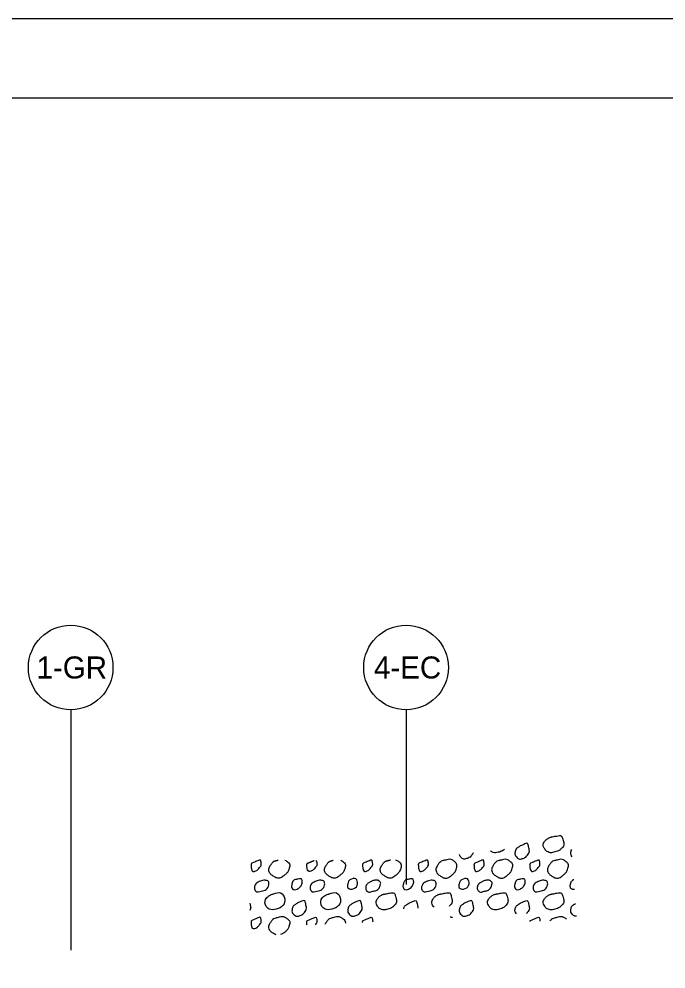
# Model space of a CAD drawing. Extents: x 0 to 3369, y -440 to 440.
# Drawn here: x 466.9 to 549, y 319.4 to 440 of the extents above; entities that cross this region are included whole.
import ezdxf

# ---------------------------------------------------------------- set-up
doc = ezdxf.new("R2010")
doc.units = 0
for name, color, linetype in [('GE_P_Alignment', 7, 'Continuous'), ('PF_X_Ground_Line', 7, 'Continuous'), ('PV_P_EOP', 7, 'Continuous'), ('SC_Scratch1', 7, 'Continuous')]:
    doc.layers.add(name, color=color, linetype=linetype)

msp = doc.modelspace()

# ---------------------------------------------------------------- linework, layer by layer
at = {"layer": 'GE_P_Alignment'}
for points, degree in [([(530.47, 335), (530.7, 335.1), (530.94, 335.2), (531.17, 335.3), (531.42, 335.4), (531.53, 334.87), (531.59, 334.62), (531.64, 334.36), (531.58, 334.06), (531.37, 333.81), (531.17, 333.57), (530.94, 333.46), (530.7, 333.39), (530.51, 333.33), (530.26, 333.32), (530.08, 333.5), (529.85, 333.73), (529.76, 333.99), (529.81, 334.22), (529.85, 334.4), (529.93, 334.64), (530.1, 334.76), (530.22, 334.84), (530.35, 334.92), (530.47, 335)], 3), ([(534.51, 336.16), (534.81, 336.21), (535.12, 336.27), (535.42, 336.31), (535.72, 336.35), (535.86, 335.84), (535.94, 335.55), (536.01, 335.29), (535.96, 334.98), (535.74, 334.74), (535.48, 334.44), (535.18, 334.33), (534.85, 334.23), (534.57, 334.15), (534.25, 334.12), (533.97, 334.24), (533.8, 334.31), (533.68, 334.44), (533.57, 334.6), (533.4, 334.86), (533.35, 335.23), (533.5, 335.49), (533.6, 335.65), (533.74, 335.8), (533.91, 335.91), (534.06, 336.01), (534.2, 336.09), (534.36, 336.13), (534.42, 336.14), (534.47, 336.15), (534.53, 336.16)], 3), ([(528.47, 334.55), (528.26, 334.39), (528.03, 334.31), (527.78, 334.23), (527.5, 334.15), (527.18, 334.12), (526.9, 334.24), (526.83, 334.27), (526.76, 334.31), (526.7, 334.36)], 3), ([(537.05, 333.61), (536.9, 333.81), (536.84, 334.03), (536.88, 334.22), (536.9, 334.32), (536.93, 334.43), (536.99, 334.53)], 3), ([(496.4, 332.81), (496.71, 332.93), (497.03, 333.07), (497.35, 333.19), (497.5, 333.25), (497.58, 332.9), (497.6, 332.75), (497.62, 332.55), (497.46, 332.35), (497.3, 332.15), (497.08, 331.88), (496.51, 331.69), (496.4, 331.98), (496.34, 332.14), (496.33, 332.3), (496.32, 332.46), (496.32, 332.54), (496.29, 332.63), (496.33, 332.7), (496.35, 332.74), (496.37, 332.77), (496.4, 332.81)], 3), ([(500.61, 333.19), (500.72, 333.15), (500.83, 333.07), (500.95, 332.98), (501.22, 332.76), (501.23, 332.42), (501.16, 332.18), (501.07, 331.86), (500.87, 331.56), (500.57, 331.31), (500.19, 330.98), (499.66, 330.85), (499.27, 331.08), (498.96, 331.27), (498.63, 331.55), (498.57, 331.88), (498.53, 332.09), (498.63, 332.33), (498.76, 332.52), (498.84, 332.65), (498.92, 332.79), (499.03, 332.9), (499.09, 332.95), (499.14, 333.01), (499.19, 333.06)], 3), ([(499.19, 333.06), (499.38, 333.11), (499.56, 333.15), (499.75, 333.2)], 2), ([(504.53, 333.16), (504.61, 333.07), (504.66, 332.86), (504.67, 332.75), (504.69, 332.55), (504.53, 332.35), (504.37, 332.15), (504.15, 331.88), (503.59, 331.69), (503.47, 331.98), (503.41, 332.14), (503.4, 332.3), (503.39, 332.46), (503.39, 332.54), (503.36, 332.63), (503.4, 332.7), (503.42, 332.74), (503.44, 332.77), (503.47, 332.81)], 3), ([(503.47, 332.81), (503.75, 332.92), (504.04, 333.05), (504.33, 333.16)], 2), ([(507.7, 333.18), (507.81, 333.14), (507.91, 333.07), (508.02, 332.98), (508.29, 332.76), (508.3, 332.42), (508.23, 332.18), (508.14, 331.86), (507.95, 331.56), (507.64, 331.31), (507.26, 330.98), (506.73, 330.85), (506.35, 331.08), (506.03, 331.27), (505.7, 331.55), (505.64, 331.88), (505.6, 332.09), (505.71, 332.33), (505.83, 332.52), (505.91, 332.65), (505.99, 332.79), (506.1, 332.9), (506.16, 332.95), (506.21, 333.01), (506.27, 333.06)], 3), ([(506.27, 333.06), (506.42, 333.1), (506.57, 333.14), (506.72, 333.18)], 2), ([(510.54, 332.81), (510.86, 332.93), (511.17, 333.07), (511.49, 333.19), (511.64, 333.25), (511.73, 332.9), (511.74, 332.75), (511.76, 332.55), (511.61, 332.35), (511.44, 332.15), (511.22, 331.88), (510.66, 331.69), (510.54, 331.98), (510.48, 332.14), (510.47, 332.3), (510.46, 332.46), (510.46, 332.54), (510.43, 332.63), (510.47, 332.7), (510.49, 332.74), (510.52, 332.77), (510.54, 332.81)], 3), ([(514.62, 333.24), (514.78, 333.19), (514.94, 333.11), (515.09, 332.98), (515.36, 332.76), (515.38, 332.42), (515.31, 332.18), (515.22, 331.86), (515.02, 331.56), (514.71, 331.31), (514.33, 330.98), (513.81, 330.85), (513.42, 331.08), (513.1, 331.27), (512.77, 331.55), (512.71, 331.88), (512.67, 332.09), (512.78, 332.33), (512.9, 332.52), (512.98, 332.65), (513.06, 332.79), (513.18, 332.9), (513.23, 332.95), (513.28, 333.01), (513.34, 333.06)], 3), ([(513.34, 333.06), (513.56, 333.12), (513.79, 333.18), (514.01, 333.23)], 2), ([(517.61, 332.81), (517.93, 332.93), (518.24, 333.07), (518.56, 333.19), (518.72, 333.25), (518.8, 332.9), (518.81, 332.75), (518.83, 332.55), (518.68, 332.35), (518.51, 332.15), (518.29, 331.88), (517.73, 331.69), (517.61, 331.98), (517.55, 332.14), (517.54, 332.3), (517.54, 332.46), (517.53, 332.54), (517.5, 332.63), (517.54, 332.7), (517.56, 332.74), (517.59, 332.77), (517.61, 332.81)], 3), ([(520.41, 333.06), (520.65, 333.12), (520.88, 333.18), (521.12, 333.24), (521.47, 333.33), (521.82, 333.27), (522.16, 332.98), (522.43, 332.76), (522.45, 332.42), (522.38, 332.18), (522.29, 331.86), (522.09, 331.56), (521.79, 331.31), (521.41, 330.98), (520.88, 330.85), (520.49, 331.08), (520.17, 331.27), (519.84, 331.55), (519.78, 331.88), (519.74, 332.09), (519.85, 332.33), (519.97, 332.52), (520.06, 332.65), (520.13, 332.79), (520.25, 332.9), (520.3, 332.95), (520.35, 333.01), (520.41, 333.06)], 3), ([(524.48, 334.12), (524.44, 334.01), (524.38, 333.91), (524.29, 333.81), (524.09, 333.57), (523.87, 333.46), (523.63, 333.39), (523.43, 333.33), (523.19, 333.32), (523.01, 333.5), (522.87, 333.64), (522.78, 333.79), (522.75, 333.93)], 3), ([(524.68, 332.81), (525, 332.93), (525.32, 333.07), (525.63, 333.19), (525.79, 333.25), (525.87, 332.9), (525.88, 332.75), (525.9, 332.55), (525.75, 332.35), (525.59, 332.15), (525.36, 331.88), (524.8, 331.69), (524.69, 331.98), (524.62, 332.14), (524.61, 332.3), (524.61, 332.46), (524.6, 332.54), (524.57, 332.63), (524.62, 332.7), (524.64, 332.74), (524.66, 332.77), (524.68, 332.81)], 3), ([(527.48, 333.06), (527.72, 333.12), (527.95, 333.18), (528.19, 333.24), (528.54, 333.33), (528.89, 333.27), (529.23, 332.98), (529.5, 332.76), (529.52, 332.42), (529.45, 332.18), (529.36, 331.86), (529.16, 331.56), (528.86, 331.31), (528.48, 330.98), (527.95, 330.85), (527.56, 331.08), (527.24, 331.27), (526.91, 331.55), (526.85, 331.88), (526.81, 332.09), (526.92, 332.33), (527.04, 332.52), (527.13, 332.65), (527.2, 332.79), (527.32, 332.9), (527.37, 332.95), (527.43, 333.01), (527.48, 333.06)], 3), ([(531.75, 332.81), (532.07, 332.93), (532.39, 333.07), (532.7, 333.19), (532.86, 333.25), (532.94, 332.9), (532.95, 332.75), (532.97, 332.55), (532.82, 332.35), (532.66, 332.15), (532.43, 331.88), (531.87, 331.69), (531.76, 331.98), (531.7, 332.14), (531.68, 332.3), (531.68, 332.46), (531.68, 332.54), (531.64, 332.63), (531.69, 332.7), (531.71, 332.74), (531.73, 332.77), (531.75, 332.81)], 3), ([(534.55, 333.06), (534.79, 333.12), (535.03, 333.18), (535.26, 333.24), (535.61, 333.33), (535.96, 333.27), (536.3, 332.98), (536.57, 332.76), (536.59, 332.42), (536.52, 332.18), (536.43, 331.86), (536.23, 331.56), (535.93, 331.31), (535.55, 330.98), (535.02, 330.85), (534.63, 331.08), (534.32, 331.27), (533.98, 331.55), (533.92, 331.88), (533.89, 332.09), (533.99, 332.33), (534.11, 332.52), (534.2, 332.65), (534.28, 332.79), (534.39, 332.9), (534.44, 332.95), (534.5, 333.01), (534.55, 333.06)], 3), ([(501.78, 330.71), (502.03, 330.75), (502.28, 330.79), (502.54, 330.82), (502.77, 330.85), (502.82, 330.36), (502.75, 330.17), (502.67, 329.95), (502.47, 329.73), (502.27, 329.58), (502.06, 329.42), (501.62, 329.44), (501.49, 329.69), (501.42, 329.85), (501.46, 330.03), (501.5, 330.18), (501.53, 330.29), (501.54, 330.42), (501.62, 330.51), (501.67, 330.58), (501.72, 330.64), (501.78, 330.71)], 3), ([(511.12, 330.28), (511.29, 330.36), (511.45, 330.44), (511.62, 330.53), (511.8, 330.62), (512.02, 330.64), (512.22, 330.64), (512.37, 330.65), (512.51, 330.61), (512.65, 330.48), (512.77, 330.36), (512.75, 330.2), (512.71, 330.07), (512.65, 329.86), (512.58, 329.65), (512.37, 329.48), (512.17, 329.31), (511.96, 329.29), (511.75, 329.24), (511.52, 329.19), (511.26, 329.06), (511.04, 329.25), (510.9, 329.38), (510.87, 329.54), (510.87, 329.68), (510.87, 329.82), (510.89, 329.97), (510.97, 330.08), (511.02, 330.15), (511.07, 330.21), (511.12, 330.28)], 3), ([(515.92, 330.71), (516.17, 330.75), (516.43, 330.79), (516.68, 330.82), (516.91, 330.85), (516.96, 330.36), (516.89, 330.17), (516.81, 329.95), (516.61, 329.73), (516.41, 329.58), (516.2, 329.42), (515.76, 329.44), (515.64, 329.69), (515.56, 329.85), (515.6, 330.03), (515.64, 330.18), (515.67, 330.29), (515.69, 330.42), (515.76, 330.51), (515.81, 330.58), (515.86, 330.64), (515.92, 330.71)], 3), ([(525.27, 330.28), (525.43, 330.36), (525.6, 330.44), (525.77, 330.53), (525.95, 330.62), (526.17, 330.64), (526.37, 330.64), (526.51, 330.65), (526.66, 330.61), (526.79, 330.48), (526.91, 330.36), (526.89, 330.2), (526.86, 330.07), (526.8, 329.86), (526.72, 329.65), (526.52, 329.48), (526.31, 329.31), (526.1, 329.29), (525.89, 329.24), (525.66, 329.19), (525.41, 329.06), (525.19, 329.25), (525.04, 329.38), (525.01, 329.54), (525.01, 329.68), (525.02, 329.82), (525.03, 329.97), (525.12, 330.08), (525.17, 330.15), (525.22, 330.21), (525.27, 330.28)], 3), ([(530.06, 330.71), (530.32, 330.75), (530.57, 330.79), (530.83, 330.82), (531.05, 330.85), (531.11, 330.36), (531.03, 330.17), (530.95, 329.95), (530.76, 329.73), (530.55, 329.58), (530.34, 329.42), (529.9, 329.44), (529.78, 329.69), (529.7, 329.85), (529.74, 330.03), (529.79, 330.18), (529.82, 330.29), (529.83, 330.42), (529.9, 330.51), (529.95, 330.58), (530.01, 330.64), (530.06, 330.71)], 3), ([(537.34, 329.48), (537.14, 329.46), (536.93, 329.53), (536.85, 329.69), (536.78, 329.85), (536.81, 330.03), (536.86, 330.18), (536.89, 330.29), (536.9, 330.42), (536.97, 330.51), (537.03, 330.58), (537.08, 330.64), (537.13, 330.71)], 3), ([(537.13, 330.71), (537.17, 330.72), (537.21, 330.72), (537.25, 330.73)], 2), ([(502.18, 327.73), (502.42, 327.84), (502.65, 327.94), (502.89, 328.04), (503.13, 328.14), (503.25, 327.61), (503.3, 327.36), (503.36, 327.1), (503.29, 326.8), (503.08, 326.55), (502.88, 326.31), (502.65, 326.2), (502.41, 326.12), (502.22, 326.07), (501.98, 326.06), (501.79, 326.24), (501.56, 326.47), (501.48, 326.73), (501.52, 326.96), (501.56, 327.14), (501.64, 327.38), (501.82, 327.5), (501.94, 327.58), (502.06, 327.65), (502.18, 327.73)], 3), ([(509.26, 327.73), (509.49, 327.84), (509.72, 327.94), (509.96, 328.04), (510.2, 328.14), (510.32, 327.61), (510.37, 327.36), (510.43, 327.1), (510.36, 326.8), (510.15, 326.55), (509.95, 326.31), (509.72, 326.2), (509.48, 326.12), (509.29, 326.07), (509.05, 326.06), (508.86, 326.24), (508.63, 326.47), (508.55, 326.73), (508.6, 326.96), (508.63, 327.14), (508.72, 327.38), (508.89, 327.5), (509.01, 327.58), (509.13, 327.65), (509.26, 327.73)], 3), ([(513.3, 328.9), (513.6, 328.95), (513.9, 329.01), (514.2, 329.05), (514.51, 329.09), (514.65, 328.57), (514.72, 328.29), (514.79, 328.03), (514.75, 327.72), (514.53, 327.48), (514.26, 327.18), (513.97, 327.07), (513.64, 326.97), (513.35, 326.89), (513.04, 326.86), (512.76, 326.98), (512.59, 327.05), (512.46, 327.17), (512.36, 327.33), (512.19, 327.6), (512.13, 327.97), (512.29, 328.22), (512.39, 328.39), (512.52, 328.54), (512.7, 328.65), (512.84, 328.75), (512.98, 328.83), (513.15, 328.87), (513.2, 328.88), (513.26, 328.89), (513.31, 328.9)], 3), ([(516.33, 327.73), (516.56, 327.84), (516.8, 327.94), (517.03, 328.04), (517.27, 328.14), (517.39, 327.61), (517.45, 327.36), (517.46, 327.28), (517.47, 327.19), (517.46, 327.1)], 3), ([(519.52, 327.22), (519.49, 327.25), (519.46, 327.29), (519.43, 327.33), (519.26, 327.6), (519.21, 327.97), (519.36, 328.22), (519.46, 328.39), (519.59, 328.54), (519.77, 328.65), (519.91, 328.75), (520.06, 328.83), (520.22, 328.87), (520.27, 328.88), (520.33, 328.89), (520.38, 328.9)], 3), ([(520.37, 328.9), (520.67, 328.95), (520.97, 329.01), (521.28, 329.05), (521.58, 329.09), (521.72, 328.57), (521.79, 328.29), (521.86, 328.03), (521.82, 327.72), (521.6, 327.48), (521.55, 327.42), (521.49, 327.37), (521.44, 327.32)], 3), ([(523.4, 327.73), (523.63, 327.84), (523.87, 327.94), (524.1, 328.04), (524.34, 328.14), (524.46, 327.61), (524.52, 327.36), (524.57, 327.1), (524.51, 326.8), (524.29, 326.55), (524.09, 326.31), (523.87, 326.2), (523.63, 326.12), (523.43, 326.07), (523.19, 326.06), (523.01, 326.24), (522.78, 326.47), (522.69, 326.73), (522.74, 326.96), (522.77, 327.14), (522.86, 327.38), (523.03, 327.5), (523.15, 327.58), (523.28, 327.65), (523.4, 327.73)], 3), ([(527.44, 328.9), (527.74, 328.95), (528.04, 329.01), (528.35, 329.05), (528.65, 329.09), (528.79, 328.57), (528.87, 328.29), (528.93, 328.03), (528.89, 327.72), (528.67, 327.48), (528.41, 327.18), (528.11, 327.07), (527.78, 326.97), (527.5, 326.89), (527.18, 326.86), (526.9, 326.98), (526.73, 327.05), (526.61, 327.17), (526.5, 327.33), (526.33, 327.6), (526.28, 327.97), (526.43, 328.22), (526.53, 328.39), (526.66, 328.54), (526.84, 328.65), (526.99, 328.75), (527.13, 328.83), (527.29, 328.87), (527.35, 328.88), (527.4, 328.89), (527.46, 328.9)], 3), ([(530.47, 327.73), (530.7, 327.84), (530.94, 327.94), (531.17, 328.04), (531.42, 328.14), (531.53, 327.61), (531.59, 327.36), (531.64, 327.1), (531.58, 326.8), (531.37, 326.55), (531.33, 326.51), (531.3, 326.47), (531.26, 326.44)], 3), ([(534.51, 328.9), (534.81, 328.95), (535.12, 329.01), (535.42, 329.05), (535.72, 329.09), (535.86, 328.57), (535.94, 328.29), (536.01, 328.03), (535.96, 327.72), (535.74, 327.48), (535.48, 327.18), (535.18, 327.07), (534.85, 326.97), (534.57, 326.89), (534.25, 326.86), (533.97, 326.98), (533.8, 327.05), (533.68, 327.17), (533.57, 327.33), (533.4, 327.6), (533.35, 327.97), (533.5, 328.22), (533.6, 328.39), (533.74, 328.54), (533.91, 328.65), (534.06, 328.75), (534.2, 328.83), (534.36, 328.87), (534.42, 328.88), (534.47, 328.89), (534.53, 328.9)], 3), ([(496.13, 327.75), (496.17, 327.61), (496.21, 327.46), (496.23, 327.36), (496.27, 327.18), (496.25, 326.98), (496.16, 326.79)], 3), ([(515.68, 327.01), (515.72, 327.18), (515.8, 327.39), (515.96, 327.5), (516.08, 327.58), (516.2, 327.65), (516.33, 327.73)], 3), ([(529.97, 326.37), (529.82, 326.56), (529.77, 326.77), (529.81, 326.96), (529.85, 327.14), (529.93, 327.38), (530.1, 327.5), (530.22, 327.58), (530.35, 327.65), (530.47, 327.73)], 3), ([(537.58, 326.09), (537.43, 326.08), (537.28, 326.12), (537.15, 326.24), (536.92, 326.47), (536.84, 326.73), (536.88, 326.96), (536.92, 327.14), (537, 327.38), (537.17, 327.5), (537.27, 327.56), (537.37, 327.62), (537.47, 327.69)], 3), ([(496.4, 325.54), (496.71, 325.67), (497.03, 325.81), (497.35, 325.93), (497.5, 325.99), (497.58, 325.64), (497.6, 325.49), (497.62, 325.29), (497.46, 325.09), (497.3, 324.89), (497.08, 324.62), (496.51, 324.42), (496.4, 324.72), (496.34, 324.88), (496.33, 325.04), (496.32, 325.2), (496.32, 325.28), (496.29, 325.37), (496.33, 325.44), (496.35, 325.48), (496.37, 325.51), (496.4, 325.54)], 3), ([(499.49, 323.73), (499.41, 323.75), (499.34, 323.78), (499.27, 323.82), (498.96, 324.01), (498.63, 324.29), (498.57, 324.62), (498.53, 324.83), (498.63, 325.06), (498.76, 325.26), (498.84, 325.39), (498.92, 325.53), (499.03, 325.64), (499.09, 325.69), (499.14, 325.74), (499.19, 325.8)], 3), ([(499.19, 325.8), (499.43, 325.86), (499.67, 325.92), (499.91, 325.98), (500.25, 326.07), (500.6, 326.01), (500.95, 325.72), (501.22, 325.49), (501.23, 325.16), (501.16, 324.91), (501.07, 324.6), (500.87, 324.3), (500.57, 324.04), (500.42, 323.91), (500.24, 323.82), (500.06, 323.76)], 3), ([(503.47, 325.54), (503.78, 325.67), (504.1, 325.81), (504.42, 325.93), (504.57, 325.99), (504.65, 325.64), (504.67, 325.49), (504.68, 325.32), (504.58, 325.15), (504.44, 324.98)], 3), ([(505.71, 325.05), (505.75, 325.12), (505.79, 325.19), (505.83, 325.26), (505.91, 325.39), (505.99, 325.53), (506.1, 325.64), (506.16, 325.69), (506.21, 325.74), (506.27, 325.8)], 3), ([(506.27, 325.8), (506.5, 325.86), (506.74, 325.92), (506.98, 325.98), (507.32, 326.07), (507.67, 326.01), (508.02, 325.72), (508.2, 325.57), (508.26, 325.37), (508.27, 325.19)], 3), ([(510.54, 325.54), (510.86, 325.67), (511.17, 325.81), (511.49, 325.93), (511.64, 325.99), (511.73, 325.64), (511.74, 325.49), (511.74, 325.45), (511.74, 325.41), (511.73, 325.37)], 3), ([(521.56, 326.01), (521.66, 325.99), (521.75, 325.97), (521.84, 325.92)], 2), ([(531.75, 325.54), (532.07, 325.67), (532.39, 325.81), (532.7, 325.93), (532.86, 325.99), (532.94, 325.64), (532.95, 325.49), (532.96, 325.48), (532.96, 325.47), (532.96, 325.45)], 3), ([(534.27, 325.5), (534.3, 325.55), (534.34, 325.6), (534.39, 325.64), (534.44, 325.69), (534.5, 325.74), (534.55, 325.8)], 3), ([(534.55, 325.8), (534.79, 325.86), (535.03, 325.92), (535.26, 325.98), (535.61, 326.07), (535.96, 326.01), (536.3, 325.72), (536.31, 325.72), (536.31, 325.71), (536.32, 325.71)], 3), ([(503.42, 324.92), (503.4, 325.01), (503.4, 325.11), (503.39, 325.2), (503.39, 325.28), (503.36, 325.37), (503.4, 325.44), (503.42, 325.48), (503.44, 325.51), (503.47, 325.54)], 3), ([(510.45, 325.3), (510.45, 325.35), (510.45, 325.4), (510.47, 325.44), (510.49, 325.48), (510.52, 325.51), (510.54, 325.54)], 3), ([(531.69, 325.45), (531.71, 325.49), (531.73, 325.51), (531.75, 325.54)], 2)]:
    msp.add_open_spline(points, degree=degree, dxfattribs=at)
for points in [[(496.98, 330.28), (497.48, 330.53), (498.08, 330.64), (498.5, 330.48), (498.57, 330.07), (498.23, 329.48), (497.6, 329.24), (496.9, 329.25), (496.73, 329.68), (496.83, 330.08), (496.98, 330.28)], [(504.05, 330.28), (504.55, 330.53), (505.15, 330.64), (505.57, 330.48), (505.64, 330.07), (505.3, 329.48), (504.67, 329.24), (503.97, 329.25), (503.8, 329.68), (503.9, 330.08), (504.05, 330.28)], [(508.85, 330.71), (509.61, 330.82), (509.82, 330.17), (509.34, 329.58), (508.57, 329.69), (508.57, 330.18), (508.69, 330.51), (508.85, 330.71)], [(518.19, 330.28), (518.69, 330.53), (519.3, 330.64), (519.72, 330.48), (519.79, 330.07), (519.44, 329.48), (518.82, 329.24), (518.11, 329.25), (517.94, 329.68), (518.05, 330.08), (518.19, 330.28)], [(522.99, 330.71), (523.75, 330.82), (523.96, 330.17), (523.48, 329.58), (522.71, 329.69), (522.71, 330.18), (522.83, 330.51), (522.99, 330.71)], [(532.34, 330.28), (532.84, 330.53), (533.44, 330.64), (533.86, 330.48), (533.93, 330.07), (533.59, 329.48), (532.96, 329.24), (532.26, 329.25), (532.08, 329.68), (532.19, 330.08), (532.34, 330.28)], [(499.15, 328.9), (500.06, 329.05), (500.58, 328.29), (500.39, 327.48), (499.49, 326.97), (498.61, 326.98), (498.22, 327.33), (498.14, 328.22), (498.55, 328.65), (499, 328.87), (499.17, 328.9)], [(506.22, 328.9), (507.13, 329.05), (507.65, 328.29), (507.46, 327.48), (506.57, 326.97), (505.69, 326.98), (505.29, 327.33), (505.21, 328.22), (505.62, 328.65), (506.08, 328.87), (506.24, 328.9)]]:
    msp.add_spline(points, degree=3, dxfattribs=at)
at = {"layer": 'PF_X_Ground_Line'}
msp.add_lwpolyline([(30, 430), (670, 430), (670, 10), (30, 10)], close=True, dxfattribs=at)
at = {"layer": 'PV_P_EOP'}
for p, q in [((473.42, 352.29), (473.42, 321.75)), ((515.97, 352.29), (515.97, 330.11))]:
    msp.add_line(p, q, dxfattribs=at)
for centre in [(473.42, 357.66), (515.97, 357.66)]:
    msp.add_circle(centre, 5.37, dxfattribs=at)
at = {"layer": 'SC_Scratch1'}
msp.add_lwpolyline([(0, 0), (680, 0), (680, 440), (0, 440)], close=True, dxfattribs=at)

# ---------------------------------------------------------------- texts
at = {"layer": 'PV_P_EOP'}
for s, p in [('1-GR', (469.09, 356.26)), ('4-EC', (511.9, 356.26))]:
    msp.add_text(s, height=2.8, dxfattribs=at).set_placement(p)

doc.saveas('drawing.dxf')
